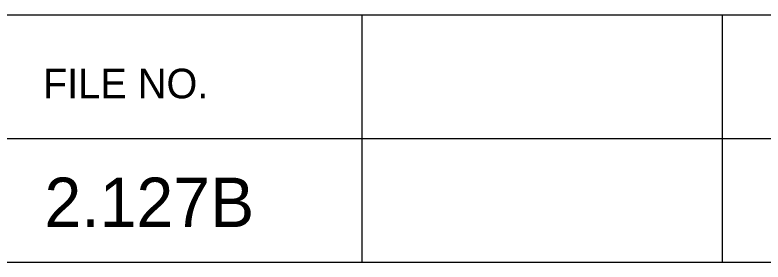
# Model space of a CAD drawing. Extents: x 1000 to 1162, y 999 to 8520.
# Drawn here: x 1145.41 to 1152.97, y 7195.05 to 7197.55 of the extents above; entities that cross this region are included whole.
import ezdxf

# ---------------------------------------------------------------- set-up
doc = ezdxf.new("R2010")
doc.units = 0
doc.layers.add('Level 20', color=7, linetype='Continuous')
doc.layers.add('Level 3', color=7, linetype='Continuous')

msp = doc.modelspace()

# ---------------------------------------------------------------- linework, layer by layer
at = {"layer": 'Level 3'}
for p, q in [((1133.055, 7197.5458), (1161.555, 7197.5458)), ((1133.055, 7197.5458), (1161.555, 7197.5458)), ((1133.055, 7197.5458), (1161.555, 7197.5458)), ((1133.055, 7197.5458), (1161.555, 7197.5458)), ((1133.055, 7197.5458), (1161.555, 7197.5458)), ((1133.055, 7197.5458), (1161.555, 7197.5458)), ((1133.055, 7197.5458), (1161.555, 7197.5458)), ((1133.055, 7197.5458), (1161.555, 7197.5458)), ((1133.055, 7197.5458), (1161.555, 7197.5458)), ((1133.055, 7197.5458), (1161.555, 7197.5458)), ((1133.055, 7197.5458), (1161.555, 7197.5458)), ((1133.055, 7197.5458), (1161.555, 7197.5458)), ((1133.055, 7197.5458), (1161.555, 7197.5458)), ((1133.055, 7197.5458), (1161.555, 7197.5458)), ((1133.055, 7197.5458), (1161.555, 7197.5458)), ((1133.055, 7197.5458), (1161.555, 7197.5458)), ((1133.055, 7197.5458), (1161.555, 7197.5458)), ((1133.055, 7197.5458), (1161.555, 7197.5458)), ((1133.055, 7197.5458), (1161.555, 7197.5458)), ((1133.055, 7197.5458), (1161.555, 7197.5458)), ((1133.055, 7197.5458), (1161.555, 7197.5458)), ((1133.055, 7197.5458), (1161.555, 7197.5458)), ((1133.055, 7197.5458), (1161.555, 7197.5458)), ((1133.055, 7197.5458), (1161.555, 7197.5458)), ((1133.055, 7197.5458), (1161.555, 7197.5458)), ((1133.055, 7197.5458), (1161.555, 7197.5458)), ((1133.055, 7197.5458), (1161.555, 7197.5458)), ((1133.055, 7197.5458), (1161.555, 7197.5458)), ((1133.055, 7197.5458), (1161.555, 7197.5458)), ((1133.055, 7197.5458), (1161.555, 7197.5458)), ((1133.055, 7197.5458), (1161.555, 7197.5458)), ((1133.055, 7197.5458), (1161.555, 7197.5458)), ((1133.055, 7197.5458), (1161.555, 7197.5458)), ((1133.055, 7197.5458), (1161.555, 7197.5458)), ((1133.055, 7197.5458), (1161.555, 7197.5458)), ((1133.055, 7197.5458), (1161.555, 7197.5458)), ((1133.055, 7197.5458), (1161.555, 7197.5458)), ((1133.055, 7197.5458), (1161.555, 7197.5458)), ((1133.055, 7197.5458), (1161.555, 7197.5458)), ((1133.055, 7197.5458), (1161.555, 7197.5458)), ((1133.055, 7197.5458), (1161.555, 7197.5458)), ((1133.055, 7197.5458), (1161.555, 7197.5458)), ((1133.055, 7197.5458), (1161.555, 7197.5458)), ((1133.055, 7197.5458), (1161.555, 7197.5458)), ((1133.055, 7197.5458), (1161.555, 7197.5458)), ((1133.055, 7197.5458), (1161.555, 7197.5458)), ((1133.055, 7197.5458), (1161.555, 7197.5458)), ((1133.055, 7197.5458), (1161.555, 7197.5458)), ((1133.055, 7197.5458), (1161.555, 7197.5458)), ((1133.055, 7197.5458), (1161.555, 7197.5458)), ((1133.055, 7197.5458), (1161.555, 7197.5458)), ((1133.055, 7197.5458), (1161.555, 7197.5458)), ((1148.9125, 7197.5458), (1148.9125, 7195.0458)), ((1148.9125, 7197.5458), (1148.9125, 7195.0458)), ((1148.9125, 7197.5458), (1148.9125, 7195.0458)), ((1148.9125, 7197.5458), (1148.9125, 7195.0458)), ((1148.9125, 7197.5458), (1148.9125, 7195.0458)), ((1148.9125, 7197.5458), (1148.9125, 7195.0458)), ((1148.9125, 7197.5458), (1148.9125, 7195.0458)), ((1148.9125, 7197.5458), (1148.9125, 7195.0458)), ((1148.9125, 7197.5458), (1148.9125, 7195.0458)), ((1148.9125, 7197.5458), (1148.9125, 7195.0458)), ((1148.9125, 7197.5458), (1148.9125, 7195.0458)), ((1148.9125, 7197.5458), (1148.9125, 7195.0458)), ((1148.9125, 7197.5458), (1148.9125, 7195.0458)), ((1148.9125, 7197.5458), (1148.9125, 7195.0458)), ((1148.9125, 7197.5458), (1148.9125, 7195.0458)), ((1148.9125, 7197.5458), (1148.9125, 7195.0458)), ((1148.9125, 7197.5458), (1148.9125, 7195.0458)), ((1148.9125, 7197.5458), (1148.9125, 7195.0458)), ((1148.9125, 7197.5458), (1148.9125, 7195.0458)), ((1148.9125, 7197.5458), (1148.9125, 7195.0458)), ((1148.9125, 7197.5458), (1148.9125, 7195.0458)), ((1148.9125, 7197.5458), (1148.9125, 7195.0458)), ((1148.9125, 7197.5458), (1148.9125, 7195.0458)), ((1148.9125, 7197.5458), (1148.9125, 7195.0458)), ((1148.9125, 7197.5458), (1148.9125, 7195.0458)), ((1148.9125, 7197.5458), (1148.9125, 7195.0458)), ((1148.9125, 7197.5458), (1148.9125, 7195.0458)), ((1148.9125, 7197.5458), (1148.9125, 7195.0458)), ((1148.9125, 7197.5458), (1148.9125, 7195.0458)), ((1148.9125, 7197.5458), (1148.9125, 7195.0458)), ((1148.9125, 7197.5458), (1148.9125, 7195.0458)), ((1148.9125, 7197.5458), (1148.9125, 7195.0458)), ((1148.9125, 7197.5458), (1148.9125, 7195.0458)), ((1148.9125, 7197.5458), (1148.9125, 7195.0458)), ((1148.9125, 7197.5458), (1148.9125, 7195.0458)), ((1148.9125, 7197.5458), (1148.9125, 7195.0458)), ((1148.9125, 7197.5458), (1148.9125, 7195.0458)), ((1148.9125, 7197.5458), (1148.9125, 7195.0458)), ((1148.9125, 7197.5458), (1148.9125, 7195.0458)), ((1148.9125, 7197.5458), (1148.9125, 7195.0458)), ((1148.9125, 7197.5458), (1148.9125, 7195.0458)), ((1148.9125, 7197.5458), (1148.9125, 7195.0458)), ((1148.9125, 7197.5458), (1148.9125, 7195.0458)), ((1148.9125, 7197.5458), (1148.9125, 7195.0458)), ((1148.9125, 7197.5458), (1148.9125, 7195.0458)), ((1148.9125, 7197.5458), (1148.9125, 7195.0458)), ((1148.9125, 7197.5458), (1148.9125, 7195.0458)), ((1148.9125, 7197.5458), (1148.9125, 7195.0458)), ((1148.9125, 7197.5458), (1148.9125, 7195.0458)), ((1148.9125, 7197.5458), (1148.9125, 7195.0458)), ((1148.9125, 7197.5458), (1148.9125, 7195.0458)), ((1148.9125, 7197.5458), (1148.9125, 7195.0458)), ((1152.5542, 7197.5458), (1152.5542, 7195.0458)), ((1152.5542, 7197.5458), (1152.5542, 7195.0458)), ((1152.5542, 7197.5458), (1152.5542, 7195.0458)), ((1152.5542, 7197.5458), (1152.5542, 7195.0458)), ((1152.5542, 7197.5458), (1152.5542, 7195.0458)), ((1152.5542, 7197.5458), (1152.5542, 7195.0458)), ((1152.5542, 7197.5458), (1152.5542, 7195.0458)), ((1152.5542, 7197.5458), (1152.5542, 7195.0458)), ((1152.5542, 7197.5458), (1152.5542, 7195.0458)), ((1152.5542, 7197.5458), (1152.5542, 7195.0458)), ((1152.5542, 7197.5458), (1152.5542, 7195.0458)), ((1152.5542, 7197.5458), (1152.5542, 7195.0458)), ((1152.5542, 7197.5458), (1152.5542, 7195.0458)), ((1152.5542, 7197.5458), (1152.5542, 7195.0458)), ((1152.5542, 7197.5458), (1152.5542, 7195.0458)), ((1152.5542, 7197.5458), (1152.5542, 7195.0458)), ((1152.5542, 7197.5458), (1152.5542, 7195.0458)), ((1152.5542, 7197.5458), (1152.5542, 7195.0458)), ((1152.5542, 7197.5458), (1152.5542, 7195.0458)), ((1152.5542, 7197.5458), (1152.5542, 7195.0458)), ((1152.5542, 7197.5458), (1152.5542, 7195.0458)), ((1152.5542, 7197.5458), (1152.5542, 7195.0458)), ((1152.5542, 7197.5458), (1152.5542, 7195.0458)), ((1152.5542, 7197.5458), (1152.5542, 7195.0458)), ((1152.5542, 7197.5458), (1152.5542, 7195.0458)), ((1152.5542, 7197.5458), (1152.5542, 7195.0458)), ((1152.5542, 7197.5458), (1152.5542, 7195.0458)), ((1152.5542, 7197.5458), (1152.5542, 7195.0458)), ((1152.5542, 7197.5458), (1152.5542, 7195.0458)), ((1152.5542, 7197.5458), (1152.5542, 7195.0458)), ((1152.5542, 7197.5458), (1152.5542, 7195.0458)), ((1152.5542, 7197.5458), (1152.5542, 7195.0458)), ((1152.5542, 7197.5458), (1152.5542, 7195.0458)), ((1152.5542, 7197.5458), (1152.5542, 7195.0458)), ((1152.5542, 7197.5458), (1152.5542, 7195.0458)), ((1152.5542, 7197.5458), (1152.5542, 7195.0458)), ((1152.5542, 7197.5458), (1152.5542, 7195.0458)), ((1152.5542, 7197.5458), (1152.5542, 7195.0458)), ((1152.5542, 7197.5458), (1152.5542, 7195.0458)), ((1152.5542, 7197.5458), (1152.5542, 7195.0458)), ((1152.5542, 7197.5458), (1152.5542, 7195.0458)), ((1152.5542, 7197.5458), (1152.5542, 7195.0458)), ((1152.5542, 7197.5458), (1152.5542, 7195.0458)), ((1152.5542, 7197.5458), (1152.5542, 7195.0458)), ((1152.5542, 7197.5458), (1152.5542, 7195.0458)), ((1152.5542, 7197.5458), (1152.5542, 7195.0458)), ((1152.5542, 7197.5458), (1152.5542, 7195.0458)), ((1152.5542, 7197.5458), (1152.5542, 7195.0458)), ((1152.5542, 7197.5458), (1152.5542, 7195.0458)), ((1152.5542, 7197.5458), (1152.5542, 7195.0458)), ((1152.5542, 7197.5458), (1152.5542, 7195.0458)), ((1152.5542, 7197.5458), (1152.5542, 7195.0458)), ((1133.055, 7196.2958), (1161.555, 7196.2958)), ((1133.055, 7196.2958), (1161.555, 7196.2958)), ((1133.055, 7196.2958), (1161.555, 7196.2958)), ((1133.055, 7196.2958), (1161.555, 7196.2958)), ((1133.055, 7196.2958), (1161.555, 7196.2958)), ((1133.055, 7196.2958), (1161.555, 7196.2958)), ((1133.055, 7196.2958), (1161.555, 7196.2958)), ((1133.055, 7196.2958), (1161.555, 7196.2958)), ((1133.055, 7196.2958), (1161.555, 7196.2958)), ((1133.055, 7196.2958), (1161.555, 7196.2958)), ((1133.055, 7196.2958), (1161.555, 7196.2958)), ((1133.055, 7196.2958), (1161.555, 7196.2958)), ((1133.055, 7196.2958), (1161.555, 7196.2958)), ((1133.055, 7196.2958), (1161.555, 7196.2958)), ((1133.055, 7196.2958), (1161.555, 7196.2958)), ((1133.055, 7196.2958), (1161.555, 7196.2958)), ((1133.055, 7196.2958), (1161.555, 7196.2958)), ((1133.055, 7196.2958), (1161.555, 7196.2958)), ((1133.055, 7196.2958), (1161.555, 7196.2958)), ((1133.055, 7196.2958), (1161.555, 7196.2958)), ((1133.055, 7196.2958), (1161.555, 7196.2958)), ((1133.055, 7196.2958), (1161.555, 7196.2958)), ((1133.055, 7196.2958), (1161.555, 7196.2958)), ((1133.055, 7196.2958), (1161.555, 7196.2958)), ((1133.055, 7196.2958), (1161.555, 7196.2958)), ((1133.055, 7196.2958), (1161.555, 7196.2958)), ((1133.055, 7196.2958), (1161.555, 7196.2958)), ((1133.055, 7196.2958), (1161.555, 7196.2958)), ((1133.055, 7196.2958), (1161.555, 7196.2958)), ((1133.055, 7196.2958), (1161.555, 7196.2958)), ((1133.055, 7196.2958), (1161.555, 7196.2958)), ((1133.055, 7196.2958), (1161.555, 7196.2958)), ((1133.055, 7196.2958), (1161.555, 7196.2958)), ((1133.055, 7196.2958), (1161.555, 7196.2958)), ((1133.055, 7196.2958), (1161.555, 7196.2958)), ((1133.055, 7196.2958), (1161.555, 7196.2958)), ((1133.055, 7196.2958), (1161.555, 7196.2958)), ((1133.055, 7196.2958), (1161.555, 7196.2958)), ((1133.055, 7196.2958), (1161.555, 7196.2958)), ((1133.055, 7196.2958), (1161.555, 7196.2958)), ((1133.055, 7196.2958), (1161.555, 7196.2958)), ((1133.055, 7196.2958), (1161.555, 7196.2958)), ((1133.055, 7196.2958), (1161.555, 7196.2958)), ((1133.055, 7196.2958), (1161.555, 7196.2958)), ((1133.055, 7196.2958), (1161.555, 7196.2958)), ((1133.055, 7196.2958), (1161.555, 7196.2958)), ((1133.055, 7196.2958), (1161.555, 7196.2958)), ((1133.055, 7196.2958), (1161.555, 7196.2958)), ((1133.055, 7196.2958), (1161.555, 7196.2958)), ((1133.055, 7196.2958), (1161.555, 7196.2958)), ((1133.055, 7196.2958), (1161.555, 7196.2958)), ((1133.055, 7196.2958), (1161.555, 7196.2958)), ((1133.055, 7195.0458), (1161.555, 7195.0458)), ((1133.055, 7195.0458), (1161.555, 7195.0458)), ((1133.055, 7195.0458), (1161.555, 7195.0458)), ((1133.055, 7195.0458), (1161.555, 7195.0458)), ((1133.055, 7195.0458), (1161.555, 7195.0458)), ((1133.055, 7195.0458), (1161.555, 7195.0458)), ((1133.055, 7195.0458), (1161.555, 7195.0458)), ((1133.055, 7195.0458), (1161.555, 7195.0458)), ((1133.055, 7195.0458), (1161.555, 7195.0458)), ((1133.055, 7195.0458), (1161.555, 7195.0458)), ((1133.055, 7195.0458), (1161.555, 7195.0458)), ((1133.055, 7195.0458), (1161.555, 7195.0458)), ((1133.055, 7195.0458), (1161.555, 7195.0458)), ((1133.055, 7195.0458), (1161.555, 7195.0458)), ((1133.055, 7195.0458), (1161.555, 7195.0458)), ((1133.055, 7195.0458), (1161.555, 7195.0458)), ((1133.055, 7195.0458), (1161.555, 7195.0458)), ((1133.055, 7195.0458), (1161.555, 7195.0458)), ((1133.055, 7195.0458), (1161.555, 7195.0458)), ((1133.055, 7195.0458), (1161.555, 7195.0458)), ((1133.055, 7195.0458), (1161.555, 7195.0458)), ((1133.055, 7195.0458), (1161.555, 7195.0458)), ((1133.055, 7195.0458), (1161.555, 7195.0458)), ((1133.055, 7195.0458), (1161.555, 7195.0458)), ((1133.055, 7195.0458), (1161.555, 7195.0458)), ((1133.055, 7195.0458), (1161.555, 7195.0458)), ((1133.055, 7195.0458), (1161.555, 7195.0458)), ((1133.055, 7195.0458), (1161.555, 7195.0458)), ((1133.055, 7195.0458), (1161.555, 7195.0458)), ((1133.055, 7195.0458), (1161.555, 7195.0458)), ((1133.055, 7195.0458), (1161.555, 7195.0458)), ((1133.055, 7195.0458), (1161.555, 7195.0458)), ((1133.055, 7195.0458), (1161.555, 7195.0458)), ((1133.055, 7195.0458), (1161.555, 7195.0458)), ((1133.055, 7195.0458), (1161.555, 7195.0458)), ((1133.055, 7195.0458), (1161.555, 7195.0458)), ((1133.055, 7195.0458), (1161.555, 7195.0458)), ((1133.055, 7195.0458), (1161.555, 7195.0458)), ((1133.055, 7195.0458), (1161.555, 7195.0458)), ((1133.055, 7195.0458), (1161.555, 7195.0458)), ((1133.055, 7195.0458), (1161.555, 7195.0458)), ((1133.055, 7195.0458), (1161.555, 7195.0458)), ((1133.055, 7195.0458), (1161.555, 7195.0458)), ((1133.055, 7195.0458), (1161.555, 7195.0458)), ((1133.055, 7195.0458), (1161.555, 7195.0458)), ((1133.055, 7195.0458), (1161.555, 7195.0458)), ((1133.055, 7195.0458), (1161.555, 7195.0458)), ((1133.055, 7195.0458), (1161.555, 7195.0458)), ((1133.055, 7195.0458), (1161.555, 7195.0458)), ((1133.055, 7195.0458), (1161.555, 7195.0458)), ((1133.055, 7195.0458), (1161.555, 7195.0458)), ((1133.055, 7195.0458), (1161.555, 7195.0458))]:
    msp.add_line(p, q, dxfattribs=at)

# ---------------------------------------------------------------- texts
at = {"layer": 'Level 20'}
msp.add_text('2.127B', height=0.5, dxfattribs=at).set_placement((1145.7068, 7195.4))
at = {"layer": 'Level 3'}
msp.add_text('FILE NO.', height=0.3, dxfattribs=at).set_placement((1145.6908, 7196.7021))
msp.add_text('FILE NO.', height=0.3, dxfattribs=at).set_placement((1145.6908, 7196.7021))
msp.add_text('FILE NO.', height=0.3, dxfattribs=at).set_placement((1145.6908, 7196.7021))
msp.add_text('FILE NO.', height=0.3, dxfattribs=at).set_placement((1145.6908, 7196.7021))
msp.add_text('FILE NO.', height=0.3, dxfattribs=at).set_placement((1145.6908, 7196.7021))
msp.add_text('FILE NO.', height=0.3, dxfattribs=at).set_placement((1145.6908, 7196.7021))
msp.add_text('FILE NO.', height=0.3, dxfattribs=at).set_placement((1145.6908, 7196.7021))
msp.add_text('FILE NO.', height=0.3, dxfattribs=at).set_placement((1145.6908, 7196.7021))
msp.add_text('FILE NO.', height=0.3, dxfattribs=at).set_placement((1145.6908, 7196.7021))
msp.add_text('FILE NO.', height=0.3, dxfattribs=at).set_placement((1145.6908, 7196.7021))
msp.add_text('FILE NO.', height=0.3, dxfattribs=at).set_placement((1145.6908, 7196.7021))
msp.add_text('FILE NO.', height=0.3, dxfattribs=at).set_placement((1145.6908, 7196.7021))
msp.add_text('FILE NO.', height=0.3, dxfattribs=at).set_placement((1145.6908, 7196.7021))
msp.add_text('FILE NO.', height=0.3, dxfattribs=at).set_placement((1145.6908, 7196.7021))
msp.add_text('FILE NO.', height=0.3, dxfattribs=at).set_placement((1145.6908, 7196.7021))
msp.add_text('FILE NO.', height=0.3, dxfattribs=at).set_placement((1145.6908, 7196.7021))
msp.add_text('FILE NO.', height=0.3, dxfattribs=at).set_placement((1145.6908, 7196.7021))
msp.add_text('FILE NO.', height=0.3, dxfattribs=at).set_placement((1145.6908, 7196.7021))
msp.add_text('FILE NO.', height=0.3, dxfattribs=at).set_placement((1145.6908, 7196.7021))
msp.add_text('FILE NO.', height=0.3, dxfattribs=at).set_placement((1145.6908, 7196.7021))
msp.add_text('FILE NO.', height=0.3, dxfattribs=at).set_placement((1145.6908, 7196.7021))
msp.add_text('FILE NO.', height=0.3, dxfattribs=at).set_placement((1145.6908, 7196.7021))
msp.add_text('FILE NO.', height=0.3, dxfattribs=at).set_placement((1145.6908, 7196.7021))
msp.add_text('FILE NO.', height=0.3, dxfattribs=at).set_placement((1145.6908, 7196.7021))
msp.add_text('FILE NO.', height=0.3, dxfattribs=at).set_placement((1145.6908, 7196.7021))
msp.add_text('FILE NO.', height=0.3, dxfattribs=at).set_placement((1145.6908, 7196.7021))
msp.add_text('FILE NO.', height=0.3, dxfattribs=at).set_placement((1145.6908, 7196.7021))
msp.add_text('FILE NO.', height=0.3, dxfattribs=at).set_placement((1145.6908, 7196.7021))
msp.add_text('FILE NO.', height=0.3, dxfattribs=at).set_placement((1145.6908, 7196.7021))
msp.add_text('FILE NO.', height=0.3, dxfattribs=at).set_placement((1145.6908, 7196.7021))
msp.add_text('FILE NO.', height=0.3, dxfattribs=at).set_placement((1145.6908, 7196.7021))
msp.add_text('FILE NO.', height=0.3, dxfattribs=at).set_placement((1145.6908, 7196.7021))
msp.add_text('FILE NO.', height=0.3, dxfattribs=at).set_placement((1145.6908, 7196.7021))
msp.add_text('FILE NO.', height=0.3, dxfattribs=at).set_placement((1145.6908, 7196.7021))
msp.add_text('FILE NO.', height=0.3, dxfattribs=at).set_placement((1145.6908, 7196.7021))
msp.add_text('FILE NO.', height=0.3, dxfattribs=at).set_placement((1145.6908, 7196.7021))
msp.add_text('FILE NO.', height=0.3, dxfattribs=at).set_placement((1145.6908, 7196.7021))
msp.add_text('FILE NO.', height=0.3, dxfattribs=at).set_placement((1145.6908, 7196.7021))
msp.add_text('FILE NO.', height=0.3, dxfattribs=at).set_placement((1145.6908, 7196.7021))
msp.add_text('FILE NO.', height=0.3, dxfattribs=at).set_placement((1145.6908, 7196.7021))
msp.add_text('FILE NO.', height=0.3, dxfattribs=at).set_placement((1145.6908, 7196.7021))
msp.add_text('FILE NO.', height=0.3, dxfattribs=at).set_placement((1145.6908, 7196.7021))
msp.add_text('FILE NO.', height=0.3, dxfattribs=at).set_placement((1145.6908, 7196.7021))
msp.add_text('FILE NO.', height=0.3, dxfattribs=at).set_placement((1145.6908, 7196.7021))
msp.add_text('FILE NO.', height=0.3, dxfattribs=at).set_placement((1145.6908, 7196.7021))
msp.add_text('FILE NO.', height=0.3, dxfattribs=at).set_placement((1145.6908, 7196.7021))
msp.add_text('FILE NO.', height=0.3, dxfattribs=at).set_placement((1145.6908, 7196.7021))
msp.add_text('FILE NO.', height=0.3, dxfattribs=at).set_placement((1145.6908, 7196.7021))
msp.add_text('FILE NO.', height=0.3, dxfattribs=at).set_placement((1145.6908, 7196.7021))
msp.add_text('FILE NO.', height=0.3, dxfattribs=at).set_placement((1145.6908, 7196.7021))
msp.add_text('FILE NO.', height=0.3, dxfattribs=at).set_placement((1145.6908, 7196.7021))
msp.add_text('FILE NO.', height=0.3, dxfattribs=at).set_placement((1145.6908, 7196.7021))

doc.saveas('drawing.dxf')
